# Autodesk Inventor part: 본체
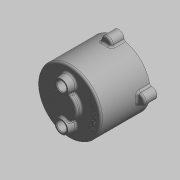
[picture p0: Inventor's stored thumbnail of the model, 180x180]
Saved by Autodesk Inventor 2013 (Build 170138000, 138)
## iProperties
Created: 2015-11
Part Number: 본체
Document SubType Name: 모델링
Designer: mdu
Material: 알루미늄 6061
Density: 2.71 g/cm^3
변환 표준: STEP AP214IS
파일 이름: C:\Users\SeoGD\Desktop\?쒗뿕\紐몄껜.stp
전처리기: Build: 253, Release: 2010 SP1 - Date: Wed 07/29/2009
전송 단위: 밀리미터
불확실성: 0.01
Author: mdu
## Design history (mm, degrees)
sketch "스케치2"
  geometry: C1 r 50 at (0, 0); 1 further point
  constraints: 1 centre point, 1 coincident
  dimensions: "d9" = 100 diameter of C1
extrude "돌출2" new body sketch "스케치2" distance "d10" = 78.5; taper "d11" = 0 deg
feature "쉘1" dims "d12" = 5
sketch "스케치3" dims "d13" = 55
  geometry: C1 r 7.5 at (0, 27.5); C2 r 12.5 at (0, 27.5); 2 further points
  constraints: 2 centre point, 2 coincident, 2 vertical alignment, 2 other
  dimensions: "d14" = 15 diameter of C1; "d15" = 25 diameter of C2
extrude "돌출3" join sketch "스케치3" distance "d16" = 12; taper "d17" = -10 deg
hole "구멍2" diameter "d20" = 15; stored, may be unused: countersink angle "d24" = 90 deg, drill point angle "d26" = 118 deg; dims "d18" = 10, "d19" = 10, "d21" = 6, "d22" = 4, "d23" = 2, "d25" = 15
chamfer "모따기1" distance "d27" = 1; stored, may be unused: second distance "d28" = 2, angle "d29" = 45 deg
sketch "스케치4"
  geometry: L1 (0, 0)-(0, 86.5); L2 (0, 68.5)-(13.16, 68.5); L3 (-45, 73.5)-(45, 73.5) reference; L4 (-50, 78.5)-(50, 78.5) reference; L5 (13.16, 68.5)-(14.5, 73.5); L6 (20, 78.5)-(20, 86.5); L7 (20, 86.5)-(0, 86.5); L8 (20, 78.5)-(14.5, 73.5)
  constraints: 12 end point, 3 point on line, 2 perpendicular, 1 vertical
  dimensions: "d34" = 40 diameter of L6 L1; "d35" = 105 deg angle of L5 L3; "d36" = 5 distance between parallel lines of L2 L3; "d37" = 8 distance between parallel lines of L7 L4; "d51" = 29 diameter of L5.end L1
revolve "회전1" sketch "스케치4" stored, may be unused: angle "d38" = 90 deg
hole "구멍3" diameter "d41" = 15; stored, may be unused: countersink angle "d45" = 90 deg, drill point angle "d47" = 0 deg; dims "d39" = 10, "d40" = 10, "d42" = 6, "d43" = 22, "d44" = 13, "d46" = 15
chamfer "모따기2" distance "d48" = 1; stored, may be unused: second distance "d49" = 2, angle "d50" = 45 deg
fillet "모깎기1" dims "d52" = 3
fillet "모깎기2" dims "d53" = 3, "d72" = 0.2
sketch "스케치5"
  geometry: A1 r 50 centre (0, 0) between (50, 0) and (-8.074, 49.344) reference; A2 r 8.5 centre (0, 52) between (8.074, 49.344) and (-8.074, 49.344); 1 further point
  constraints: 5 point on circle, 1 centre point, 1 horizontal alignment
  dimensions: "d54" = 90 deg dimension on point (0, 0) A2.centre A1.start; "d55" = 52 distance of A2.centre point (0, 0); "d56" = 17 diameter of A2
extrude "돌출4" join sketch "스케치5" distance "d57" = 20; taper "d58" = 0 deg
fillet "모깎기3" dims "d59" = 3
hole "구멍4" diameter "d62" = 4.134; stored, may be unused: countersink angle "d66" = 90 deg, drill point angle "d68" = 118 deg; dims "d60" = 10, "d61" = 10, "d63" = 12, "d64" = 22, "d65" = 13, "d67" = 15
sketch "스케치6"
  geometry: C1 r 47 at (0, 0) reference; C2 r 42.5 at (0, 0); 1 further point
  constraints: 1 centre point, 1 coincident, 1 other
  dimensions: "d73" = 85 diameter of C2
feature "엠보싱1" sketch "스케치6" dims "d74" = 0.5, "d75" = 0
node "솔리드1"
node "솔리드 본체"
node "곡면 본체"
pattern_circular "원형 패턴1" dims "d31" = 360 deg
pattern_circular "원형 패턴2" dims "d70" = 360 deg
node "솔리드2"
